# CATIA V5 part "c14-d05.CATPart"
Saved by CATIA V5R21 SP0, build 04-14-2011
Part number: Part1
Bounding box of the stored display mesh (mm): x -55 to 55, y -96.632 to 96.632, z -25 to 65
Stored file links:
  D:\CATIA V5R21 E-RESOURCES\CATIA-V5R21\catia-v5r21-Prts\c14_catia_v5r21_prt\c14-catia-v5r21-figr-14-18\c14-d05.CATPart
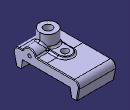
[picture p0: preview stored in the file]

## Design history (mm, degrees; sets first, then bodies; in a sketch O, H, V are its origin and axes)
Body1 (main body)
  Sketch1 on yz-plane, origin (0, 0, 0), H (0, 0, -1), V (0, 1, 0)
    construction line L1 (-49.4514, 0) -> (56.6299, 0)
    line L2 (0, 0) -> (0, 70.5918)
    point P3 (25, 75)
    line L3 (25, 75) -> (25, 90)
    point P4 (25, 90)
    line L4 (25, 90) -> (-25, 100)
    point P5 (-25, 100)
    line L5 (-25, 100) -> (-25, 0)
    point P6 (-25, 0)
    point P7 (0, 0)
    construction line L6 through (0, 0) direction (-1, 0)
    point P10 (25, -75)
    point P11 (25, -90)
    point P12 (-25, -100)
    point P13 (-25, 0)
    line L7 (0, 0) -> (0, -70.5918)
    line L8 (25, -75) -> (25, -90)
    line L9 (25, -90) -> (-25, -100)
    line L10 (-25, -100) -> (-25, 0)
    line L11 (25, 75) -> (0, 70.5918)
    point P14 (0, 70.5918)
    point P15 (0, -70.5918)
    point P16 (25, -75)
    line L12 (25, -75) -> (0, -70.5918)
    axis line L13 (25, 75) -> (-31.7388, 75)
    distance P5 P12 = 200
    length L3 = 15
    angle L11 L13 = 10
    distance L3 L5 = 50
    distance P3 P10 = 150
    angle L5 L6 = 270 (reference)
    coincidence: P6 L1, O P7, P6 P13, P10 P16
    symmetry: O P7 L1, P3 P10 L1, P4 P11 L1, P5 P12 L1, P6 P13 L1, L2 L7 L1, L3 L8 L1, L4 L9 L1, L5 L10 L1, P14 P15 L1, P3 P16 L1, L11 L12 L1
  Pad1: profile Sketch1, direction (1, 0, 0), length 55, mirrored extent
  Sketch2 on face of Pad1, origin (55, 0, 0), H (0, 1, 0), V (0, 0, 1)
    arc A1 centre (-50, 20) radius 20 from (-30.6351, 25) to (-69.3649, 25) ccw
    point P1 (-50, 20)
    line L1 (-69.3649, 25) -> (-30.6351, 25)
    reference projected line E1 (0, 25) -> (-100, 25) from edge [face of Pad1 | face of Pad1]
    reference projected point E2 (-100, 25) from vertex [face of Pad1 | face of Pad1 | face of Pad1]
    reference projected line E3 (0, 25) -> (-100, 25) from edge [face of Pad1 | face of Pad1]
    radius A1 = 20
    distance P1 E2 H = 50
    distance P1 E3 = 5
    horizontal: L1 H
    coincidence: L1 E1
  Pad2: profile Sketch2, direction (-1, 0, 0), length 55
  Sketch3 on face of Pad1, origin (0, 0, 25), H (1, 0, 0), V (0, 1, 0)
    circle A1 centre (0, -50) radius 25
    point P1 (0, -50)
    point P2 (0, -25)
    radius A1 = 25
    distance P1 H = 50
    coincidence: P1 V, A1 P2, P2 V
  Pad3: profile Sketch3, direction (0, 0, 1), length 40
  Sketch4 on face of Pad1, origin (0, 0, 25), H (1, 0, 0), V (0, 1, 0)
    line L1 (-20, -50) -> (-20, 0)
    point P2 (-20, 0)
    arc A1 centre (0, 0) radius 20 from (-20, 0) to (20, 0) cw
    point P3 (0, 0)
    line L2 (20, 0) -> (20, -50)
    line L3 (20, -50) -> (-20, -50)
    distance P3 L3 = 50
    radius A1 = 20
    coincidence: P2 H, P3 O
    vertical: L1 V, L2 V
    tangency: A1 L1, L2 A1
    horizontal: L3 H
  Pad4: profile Sketch4, direction (0, 0, 1), length 5
  Fillet1: radius 15, on edge [face of Pad1 | face of Pad1] (x2)
  Fillet2: radius 5, on edge [face of Pad1 | face of Pad4]
  Fillet3: radius 2, on edge [face of Pad4 | face of Fillet2]
  Fillet4: radius 5, on edge [face of Pad1 | face of Pad2]
  Fillet5: radius 5, on edge [face of Pad2 | face of Pad1]
  Fillet6: radius 5, on edge [face of Pad2 | face of Pad3]
  Fillet7: radius 2, on edge [face of Pad1 | face of Fillet1]; 1 edge
  Sketch5 on face of Pad1, origin (55, -45.7053, 34.0838), H (0, 1, 0), V (0, 0, 1)
    point P1 (-4.2947, -14.0838)
    reference projected arc E1 centre (-4.2947, -14.0838) radius 20 from (15.0702, -9.0838) to (-23.6596, -9.0838) ccw from edge of Pad2
    concentricity: P1 E1
  Hole1: placed by Sketch5, at (55, -50, 20) direction (-1, 0, 0), diameter 10, depth 20
  Sketch6 on face of Pad3, origin (0, -50, 65), H (1, 0, 0), V (0, 1, 0)
    point P1 (0, 0)
    reference projected circle E1 centre (0, 0) radius 25 from edge [face of Pad3 | face of Pad3]
    concentricity: P1 E1
  Hole2: placed by Sketch6, at (0, -50, 65) direction (0, 0, -1), diameter 25, through (limit type 3)
  Sketch7 on face of Pad4, origin (-2.136, -9.3115, 30), H (1, 0, 0), V (0, 1, 0)
    point P1 (2.136, 9.3115)
    reference projected arc E1 centre (2.136, 9.3115) radius 18.2918 from (20.4278, 9.3115) to (-16.1558, 9.3115) ccw from edge [face of Pad4 | face of Fillet3]
    concentricity: P1 E1
  Hole3: placed by Sketch7, at (0, 0, 30) direction (0, 0, -1), diameter 20, through (limit type 3)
